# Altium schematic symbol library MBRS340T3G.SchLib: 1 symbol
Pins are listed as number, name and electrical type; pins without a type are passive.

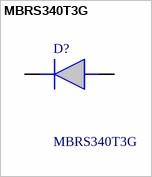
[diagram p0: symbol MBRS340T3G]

## MBRS340T3G
designator D?
Case: Epoxy, Molded; Small Compact Surface Mountable Package with J-Bend Leads; Shipped in 16 mm Tape and Reel, 2500 units per reel; Excellent Ability to Withstand Reverse Avalanche Energy Transients; Rectangular Package for Automated Handling; Highly Stable Oxide Passivated Junction; Guardring for Stress Protection Mechanical Characteristics:; Weight: 217 mg (approximately); Marking: B32, B33, B34; Finish: All External Surfaces Corrosion Resistant and Terminal Leads are Readily Solderable; Polarity: Notch; Manufacturer_Name: onsemi; Geometry.Height: 2.61mm
footprint DIOM8059X261N
pins: 1 K, 2 A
